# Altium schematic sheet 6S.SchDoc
size 431 x 279 mm; Date: Not shown in title block; ApprovedBy: Not shown in title block; CheckedBy: Not shown in title block; Author: Not shown in title block; CompanyName: Not shown in title block; Engineer: Not shown in title block; Organization: Not shown in title block; Address1: Not shown in title block; Address2: Not shown in title block; Address3: Not shown in title block; Address4: Not shown in title block; DocumentNumber: 3; Revision: Use project parameter SCH_Rev; SheetNumber: 3; SheetTotal: 5; PageSetup: Record=PageOptions¦CenterHorizontal=True¦CenterVertical=True¦PrintScale=0.64¦XCorrection=1.00¦YCorrection=1.00¦PrintKind=0¦BorderSize=5000000¦LeftOffset=0¦BottomOffset=0¦Orientation=2¦PaperLength=1000¦PaperWidth=1000¦Scale=100¦PaperSource=15¦PrintQuality=600¦MediaType=1¦DitherType=10¦PrintScaleMode=1¦PaperKind=Letter
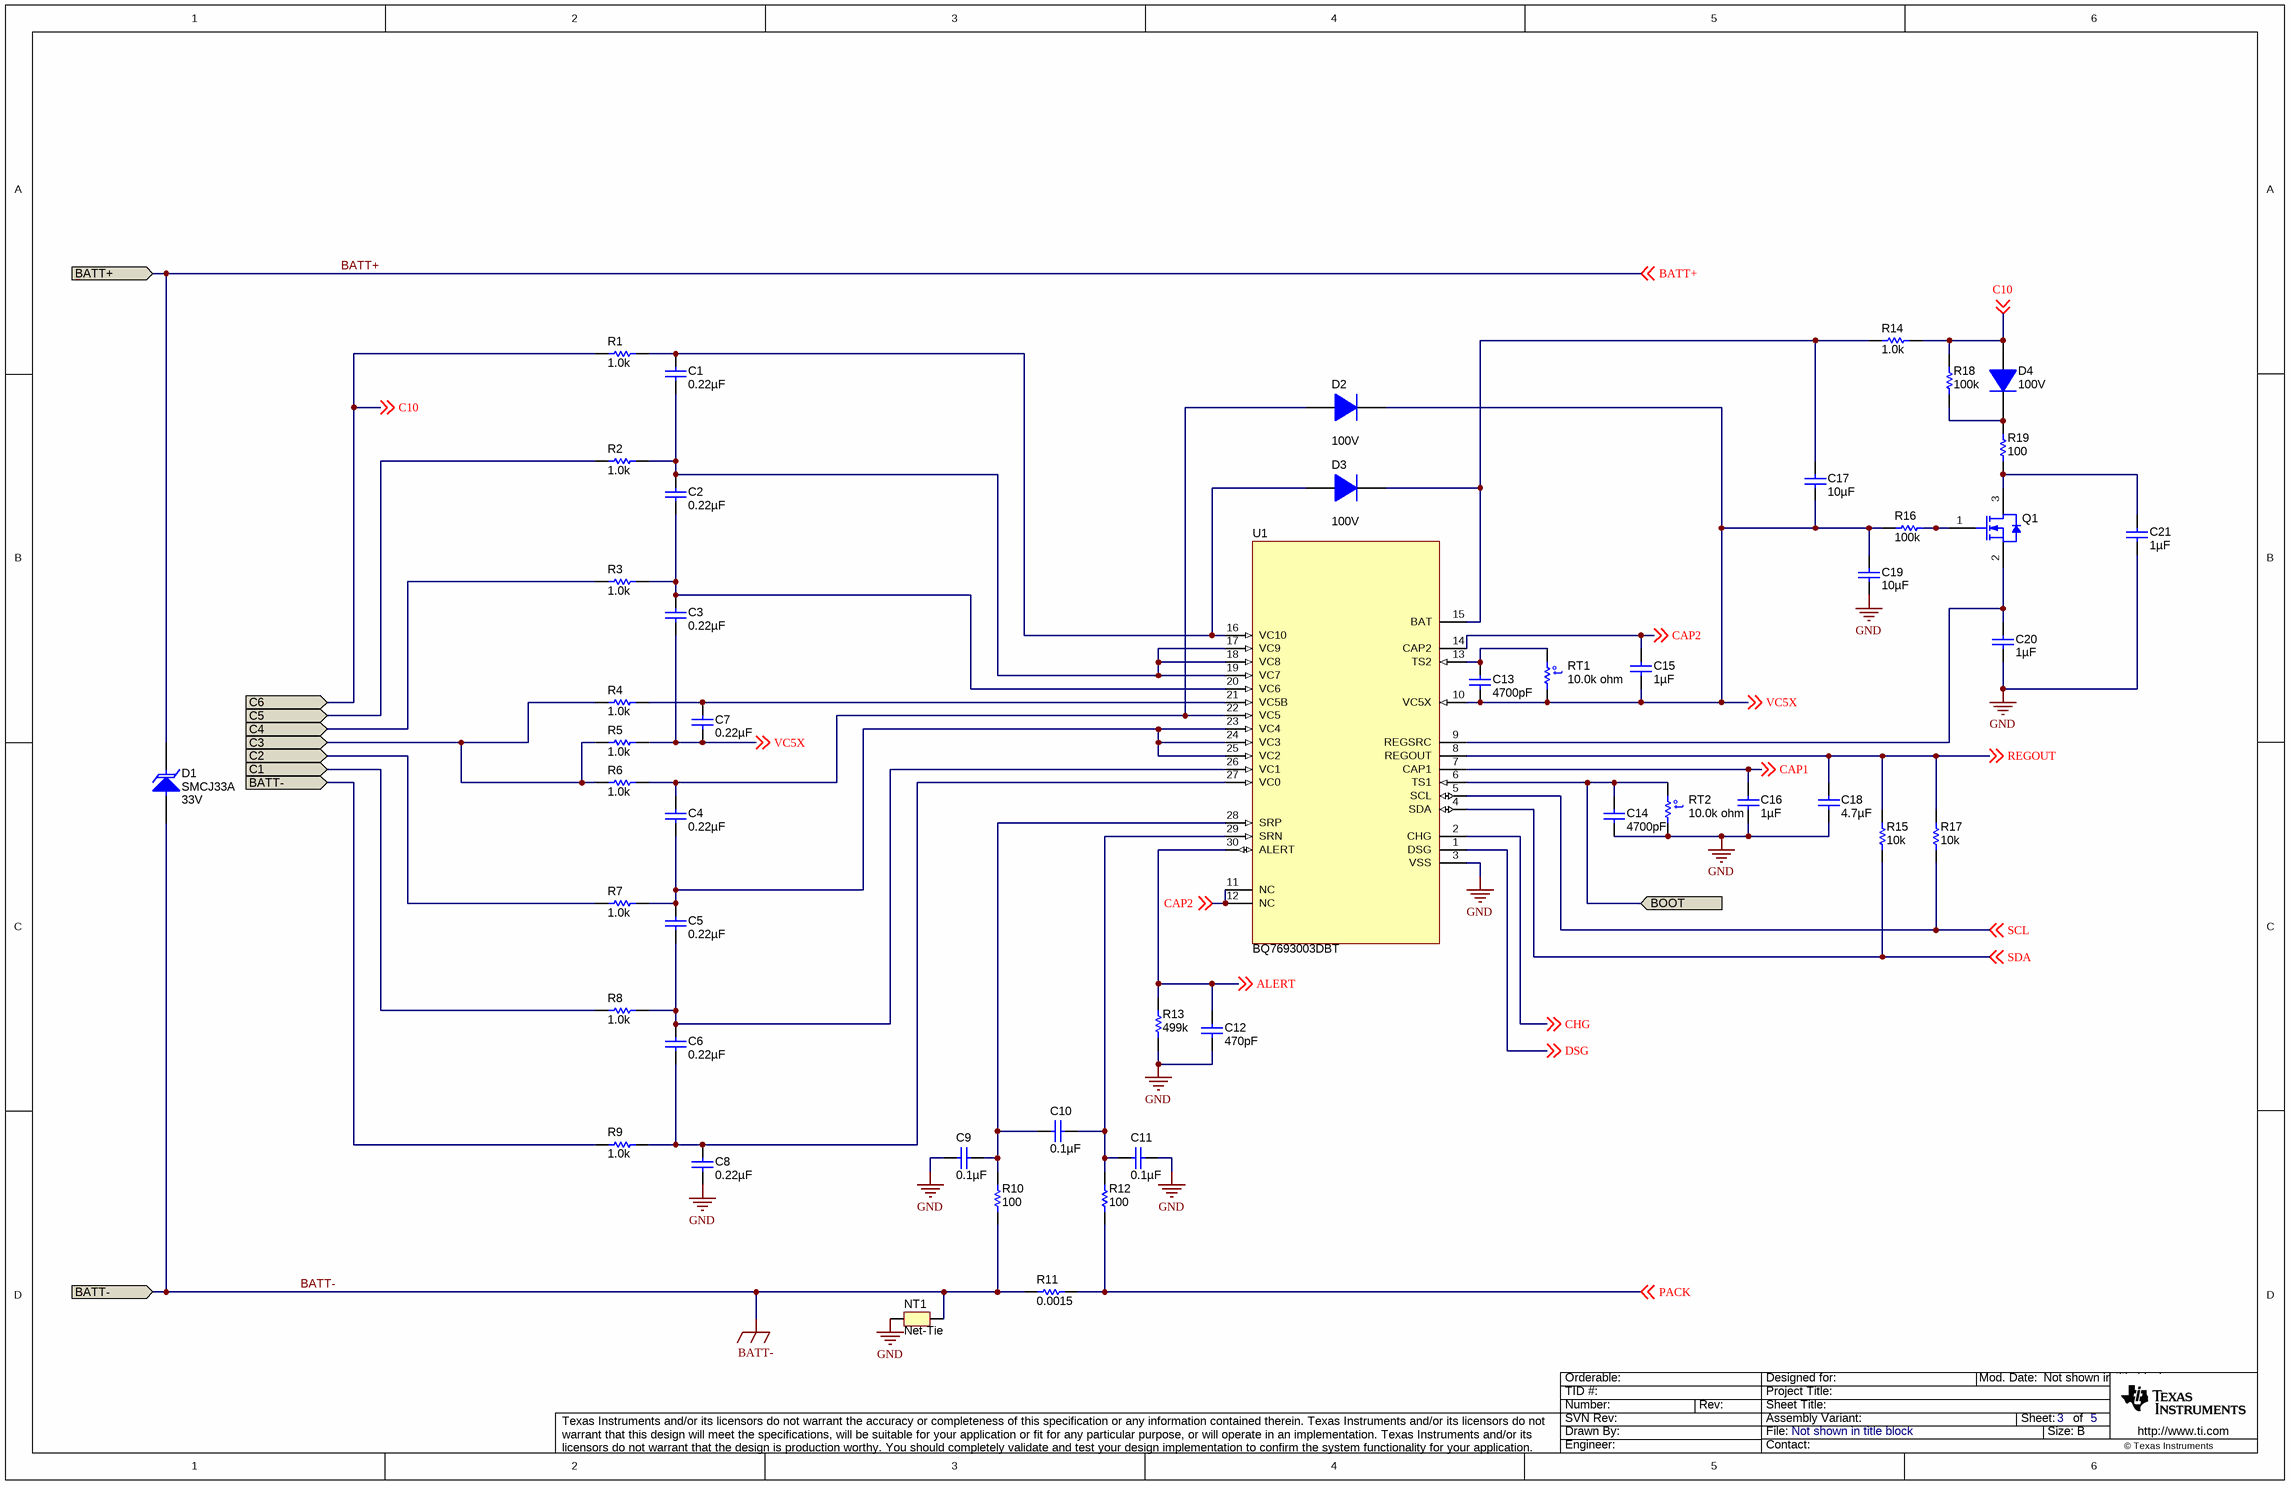
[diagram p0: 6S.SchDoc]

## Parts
C1  ValueDisplayed: 0.22µF  [0603_095]  (hidden comment: 885012206048)
C2  ValueDisplayed: 0.22µF  [0603_095]  (hidden comment: 885012206048)
C3  ValueDisplayed: 0.22µF  [0603_095]  (hidden comment: 885012206048)
C4  ValueDisplayed: 0.22µF  [0603_095]  (hidden comment: 885012206048)
C5  ValueDisplayed: 0.22µF  [0603_095]  (hidden comment: 885012206048)
C6  ValueDisplayed: 0.22µF  [0603_095]  (hidden comment: 885012206048)
C7  ValueDisplayed: 0.22µF  [0603_095]  (hidden comment: 885012206048)
C8  ValueDisplayed: 0.22µF  [0603_095]  (hidden comment: 885012206048)
C9  ValueDisplayed: 0.1µF  [0603_095]  (hidden comment: 885012206095)
C10  ValueDisplayed: 0.1µF  [0603_095]  (hidden comment: 885012206095)
C11  ValueDisplayed: 0.1µF  [0603_095]  (hidden comment: 885012206095)
C12  ValueDisplayed: 470pF  [0603_095]  (hidden comment: 885012206081)
C13  ValueDisplayed: 4700pF  [0603_095]  (hidden comment: 885012206087)
C14  ValueDisplayed: 4700pF  [0603_095]  (hidden comment: 885012206087)
C15  ValueDisplayed: 1µF  [0603_095]  (hidden comment: 885012206052)
C16  ValueDisplayed: 1µF  [0603_095]  (hidden comment: 885012206052)
C17  ValueDisplayed: 10µF  [1210]  (hidden comment: GRM32ER7YA106KA12L)
C18  ValueDisplayed: 4.7µF  [0805_145]  (hidden comment: 885012207025)
C19  ValueDisplayed: 10µF  [1210]  (hidden comment: GRM32ER7YA106KA12L)
C20  ValueDisplayed: 1µF  [0805]  (hidden comment: GRM21BR71H105KA12L)
C21  ValueDisplayed: 1µF  [0805_HV]  (hidden comment: GRM21BR71H105KA12L)
D1  SMCJ33A  value 33V  [SMC]
D2  value 100V  [SOD-123]  (hidden comment: 1N4148W-7-F)
D3  value 100V  [SOD-123]  (hidden comment: 1N4148W-7-F)
D4  value 100V  [SOD-123]  (hidden comment: 1N4148W-7-F)
NT1  Net-Tie  [Net-Tie_10mil]  (net tie, no BOM)
Q1  2N7002ET1G  [SOT-23]  (value not drawn)
R1  ValueDisplayed: 1.0k  [0603]  (hidden comment: CRCW06031K00JNEA)
R2  ValueDisplayed: 1.0k  [0603]  (hidden comment: CRCW06031K00JNEA)
R3  ValueDisplayed: 1.0k  [0603]  (hidden comment: CRCW06031K00JNEA)
R4  ValueDisplayed: 1.0k  [0603]  (hidden comment: CRCW06031K00JNEA)
R5  ValueDisplayed: 1.0k  [0603]  (hidden comment: CRCW06031K00JNEA)
R6  ValueDisplayed: 1.0k  [0603]  (hidden comment: CRCW06031K00JNEA)
R7  ValueDisplayed: 1.0k  [0603]  (hidden comment: CRCW06031K00JNEA)
R8  ValueDisplayed: 1.0k  [0603]  (hidden comment: CRCW06031K00JNEA)
R9  ValueDisplayed: 1.0k  [0603]  (hidden comment: CRCW06031K00JNEA)
R10  value 100  [0805_HV]  (hidden comment: CRCW0805100RFKEA)
R11  ValueDisplayed: 0.0015  [ULRB22512_085]  (hidden comment: ULRB22512R0015FLFSLT)
R12  value 100  [0805_HV]  (hidden comment: CRCW0805100RFKEA)
R13  ValueDisplayed: 499k  [0603]  (hidden comment: CRCW0603499KFKEA)
R14  ValueDisplayed: 1.0k  [0603]  (hidden comment: CRCW06031K00JNEA)
R15  ValueDisplayed: 10k  [0603]  (hidden comment: CRCW060310K0JNEA)
R16  value 100k  [0805_HV]  (hidden comment: CRCW0805100KFKEA)
R17  ValueDisplayed: 10k  [0603]  (hidden comment: CRCW060310K0JNEA)
R18  value 100k  [0805_HV]  (hidden comment: CRCW0805100KFKEA)
R19  value 100  [0805_HV]  (hidden comment: CRCW0805100RFKEA)
RT1  value 10.0k ohm  [Thermistor_103AT-2]  (hidden comment: 103AT-2)
RT2  value 10.0k ohm  [Thermistor_103AT-2]  (hidden comment: 103AT-2)
U1  BQ7693003DBT  [DBT0030A_N]

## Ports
BATT+, BATT-, BOOT, C1, C2, C3, C4, C5, C6

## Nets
BATT-: D1.2(A) NT1.2 R9.1 R10.1 R11.1 ; port BATT-
GND: C8.2 C9.2 C11.1 C12.2 C14.2 C16.2 C18.2 C19.2 C20.2 C21.2 NT1.1 R13.1 RT2.1 U1.3(VSS)
ALERT: C12.1 R13.2 U1.30(ALERT) ; off-sheet ALERT
BATT+: D1.1(K) ; off-sheet BATT+, port BATT+
BOOT: C14.1 RT2.2 U1.6(TS1) ; port BOOT
C1: R8.1 ; port C1
C2: R7.1 ; port C2
C3: R4.1 R5.1 R6.1 ; port C3
C4: R3.1 ; port C4
C5: R2.1 ; port C5
C10: D4.2(A) R1.1 R14.2 R18.1 ; off-sheet C10, port C6
CAP1: C16.1 U1.7(CAP1) ; off-sheet CAP1
CAP2: C15.1 U1.11(NC) U1.12(NC) U1.14(CAP2) ; off-sheet CAP2
CHG: U1.2(CHG) ; off-sheet CHG
DSG: U1.1(DSG) ; off-sheet DSG
PACK: R11.2 R12.1 ; off-sheet PACK
REGOUT: C18.1 R15.2 R17.1 U1.8(REGOUT) ; off-sheet REGOUT
SCL: R17.2 U1.5(SCL) ; off-sheet SCL
SDA: R15.1 U1.4(SDA) ; off-sheet SDA
VC5X: C3.2 C7.2 C13.2 C15.2 C17.2 C19.1 D2.1(K) R5.2 R16.1 RT1.1 U1.10(VC5X) ; off-sheet VC5X
NetC1_1: C1.1 D3.2(A) R1.2 U1.16(VC10)
NetC1_2: C1.2 C2.1 R2.2 U1.17(VC9) U1.18(VC8) U1.19(VC7)
NetC2_2: C2.2 C3.1 R3.2 U1.20(VC6)
NetC4_1: C4.1 D2.2(A) R6.2 U1.22(VC5)
NetC4_2: C4.2 C5.1 R7.2 U1.23(VC4) U1.24(VC3) U1.25(VC2)
NetC5_2: C5.2 C6.1 R8.2 U1.26(VC1)
NetC6_2: C6.2 C8.1 R9.2 U1.27(VC0)
NetC7_1: C7.1 R4.2 U1.21(VC5B)
NetC9_1: C9.1 C10.2 R10.2 U1.28(SRP)
NetC10_1: C10.1 C11.2 R12.2 U1.29(SRN)
NetC13_1: C13.1 RT1.2 U1.13(TS2)
NetC17_1: C17.1 D3.1(K) R14.1 U1.15(BAT)
NetC20_1: C20.1 Q1.2(S) U1.9(REGSRC)
NetC21_1: C21.1 Q1.3(D) R19.2
NetD4_1: D4.1(K) R18.2 R19.1
NetQ1_1: Q1.1(G) R16.2

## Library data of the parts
C1-C8 = 885012206048: CAP, CERM, 0.22 µF, 16 V, +/- 10%, X7R, 0603_095; Manufacturer: Wurth Elektronik; Polarized: N; CompType: Capacitor; Value: 0.22uF; U/M: EA; Cap_F: 0.00000022; Tolerance_%: 10; Value1: Unknown; VDC_V: 16; Value2: 16V; TaMin_C: -55; TaMax_C: 125; Cap_Case: 0603
C9-C11 = 885012206095: CAP, CERM, 0.1 µF, 50 V, +/- 10%, X7R, 0603_095; Manufacturer: Wurth Elektronik; Polarized: N; CompType: Capacitor; Value: 0.1uF; U/M: EA; Cap_F: 0.0000001; Tolerance_%: 10; Value1: Unknown; VDC_V: 50; Value2: 50V; TaMin_C: -55; TaMax_C: 125; Cap_Case: 0603
C12 = 885012206081: CAP, CERM, 470 pF, 50 V, +/- 10%, X7R, 0603_095; Manufacturer: Wurth Elektronik; Polarized: N; CompType: Capacitor; Value: 470pF; U/M: EA; Cap_F: 0.00000000047; Tolerance_%: 10; Value1: Unknown; VDC_V: 50; Value2: 50V; TaMin_C: -55; TaMax_C: 125; Cap_Case: 0603
C13 C14 = 885012206087: CAP, CERM, 4700 pF, 50 V, +/- 10%, X7R, 0603_095; Manufacturer: Wurth Elektronik; Polarized: N; CompType: Capacitor; Value: 4700pF; U/M: EA; Cap_F: 0.0000000047; Tolerance_%: 10; Value1: Unknown; VDC_V: 50; Value2: 50V; TaMin_C: -55; TaMax_C: 125; Cap_Case: 0603
C15 C16 = 885012206052: CAP, CERM, 1 µF, 16 V, +/- 10%, X7R, 0603_095; Manufacturer: Wurth Elektronik; Polarized: N; CompType: Capacitor; Value: 1uF; U/M: EA; Cap_F: 0.000001; Tolerance_%: 10; Value1: Unknown; VDC_V: 16; Value2: 16V; TaMin_C: -55; TaMax_C: 125; Cap_Case: 0603
C17 C19 = GRM32ER7YA106KA12L: CAP, CERM, 10uF, 35V, +/-10%, X7R, 1210; Manufacturer: MuRata; Polarized: N; CompType: Capacitor; U/M: EA; Cap_F: 0.00001; Tolerance_%: 10; Value1: Unknown; VDC_V: 35; TaMin_C: -55; TaMax_C: 125
C18 = 885012207025: CAP, CERM, 4.7 µF, 10 V, +/- 10%, X7R, 0805; Manufacturer: Wurth Elektronik; Polarized: N; CompType: Capacitor; Value: 4.7uF; U/M: EA; Cap_F: 0.0000047; Tolerance_%: 10; Value1: Unknown; Value2: 10V; TaMin_C: -55; TaMax_C: 125; Cap_Case: 0805
C20 = GRM21BR71H105KA12L: CAP, CERM, 1 µF, 50 V, +/- 10%, X7R, 0805; Manufacturer: MuRata; Polarized: N; CompType: Capacitor; Value: 1uF; U/M: EA; Cap_F: 0.000001; Tolerance_%: 10; Value1: Unknown; VDC_V: 50; Value2: 50V; TaMin_C: -55; TaMax_C: 125
C21 = GRM21BR71H105KA12L: CAP, CERM, 1 µF, 50 V, +/- 10%, X7R, 0805; Manufacturer: MuRata; Polarized: N; CompType: Capacitor; Value: 1uF; U/M: EA; Cap_F: 0.000001; Tolerance_%: 10; Value1: Unknown; VDC_V: 50; Value2: 50V; TaMin_C: -55; TaMax_C: 125; Cap_Case: 0805
D1 = SMCJ33A: Diode, TVS, Uni, 33 V, SMC; Manufacturer: Bourns; U/M: EA; Power_W: 5; Vr_V: 33; Value1: 5W; SizeAreaWB_mm2: 83.2686; SizeArea_mm2: 50.5686; SizeX_mm: 8.13; SizeY_mm: 6.22; SizeZ_mm: 2.6; AEC Category: Q101
D2 D3 = 1N4148W-7-F: Diode, Ultrafast, 100V, 0.15A, SOD-123; Manufacturer: Diodes Inc.; U/M: EA; Vf_V: 1.25; Value2: 1.25V; Io_A: 0.15; Vr_V: 100; TJmax_C: 150
D4 = 1N4148W-7-F: Diode, Ultrafast, 100V, 0.15A, SOD-123; Manufacturer: Diodes Inc.; U/M: EA; Vf_V: 1.25; Io_A: 0.15; Vr_V: 100; Value2: 1.25V; TJmax_C: 150
NT1 = Net-Tie: Single point connection between nets.; SymbolCreator: codlsc
Q1 = 2N7002ET1G: MOSFET, N-CH, 60 V, 0.26 A, SOT-23; Manufacturer: ON Semiconductor; Alternate Manufacturer: None; U/M: EA; ChType: N; Value: 60V; VdsMax_V: 60; Value1: 3 ohm; Rdson45_ohm: 3; Value2: 0.81 nC; QgTyp_nC: 0.81; Vgs_V: 20; IdsMax_A: 0.26
R1-R9 R14 = CRCW06031K00JNEA: RES, 1.0 k, 5%, 0.1 W, 0603; Manufacturer: Vishay-Dale; CompType: Resistor; Value: 1.0k; Res_ohm: 1000; Value_Code: 1k00; Tolerance_%: 5; Power_W: 0.1; Value2: 0.1W; VDC_V: 75; TempCo: 200 ppm/C; EIA_Code: E24; U/M: EA
R10 R12 R19 = CRCW0805100RFKEA: RES, 100 ohm, 1%, 0.125W, 0805; Manufacturer: Vishay-Dale; CompType: Resistor; Value_Code: 100R; Tolerance_%: 1; Power_W: 0.125; VDC_V: 150; TempCo: 100 ppm/C; EIA_Code: E96; U/M: EA
R11 = ULRB22512R0015FLFSLT: RES, 0.0015, 1%, 2 W, AEC-Q200 Grade 0, 2512; Manufacturer: TT Electronics/IRC; CompType: Resistor; Value: 0.0015; Value_Code: 1L500; Tolerance_%: 1; Power_W: 2; Value2: 2W; TempCo: 50 ppm/C; U/M: EA; AEC Category: Q200; AEC Qualified: Y; AEC Grade: 0
R13 = CRCW0603499KFKEA: RES, 499 k, 1%, 0.1 W, 0603; Manufacturer: Vishay-Dale; CompType: Resistor; Value: 499k; Res_ohm: 499000; Tolerance_%: 1; Power_W: 0.1; Value2: 0.1W; VDC_V: 75; TempCo: 100 ppm/C; EIA_Code: E96; U/M: EA
R15 R17 = CRCW060310K0JNEA: RES, 10 k, 5%, 0.1 W, 0603; Manufacturer: Vishay-Dale; CompType: Resistor; Value: 10k; Res_ohm: 10000; Value_Code: 10k0; Tolerance_%: 5; Power_W: 0.1; Value2: 0.1W; VDC_V: 75; TempCo: 200 ppm/C; EIA_Code: E24; U/M: EA
R16 R18 = CRCW0805100KFKEA: RES, 100k ohm, 1%, 0.125W, 0805; Manufacturer: Vishay-Dale; CompType: Resistor; Res_ohm: 100000; Tolerance_%: 1; Power_W: 0.125; VDC_V: 150; TempCo: 100 ppm/C; EIA_Code: E96; U/M: EA
RT1 RT2 = 103at-2: Thermistor NTC, 10.0k ohm, 1%, Disc, 5x8.4 mm; Manufacturer: SEMITEC Corporation; Tolerance_%: 1; Power_W: 0.01; TaMin_C: -50; TaMax_C: 110; U/M: EA
U1 = BQ7693003DBT: Battery Monitor for Lithium-Ion and Phosphate Battery Packs, DBT0030A; Manufacturer: Texas Instruments; SymbolCreator: a0799628; CompType: IC; U/M: EA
